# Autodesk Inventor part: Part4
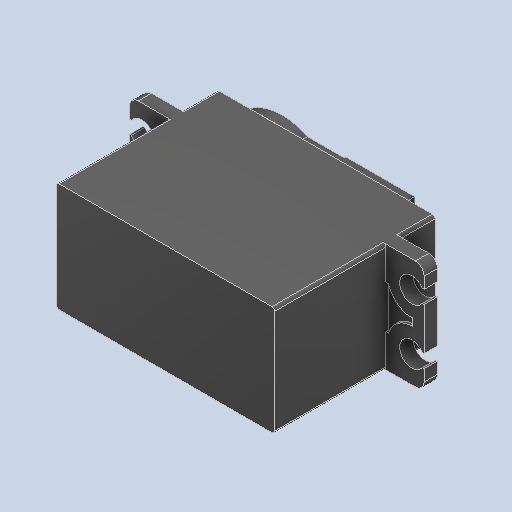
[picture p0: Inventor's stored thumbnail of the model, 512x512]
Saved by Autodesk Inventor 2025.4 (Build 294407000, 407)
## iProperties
Created: 2026-09
Part Number: Part4
Material: Generic
Document SubType Name: Modeling
Designer: AdminForWorker
Density: 1 g/cm^3
Appearance: Default
Author: AdminForWorker
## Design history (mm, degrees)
feature "Body1"
body "Solid1"
